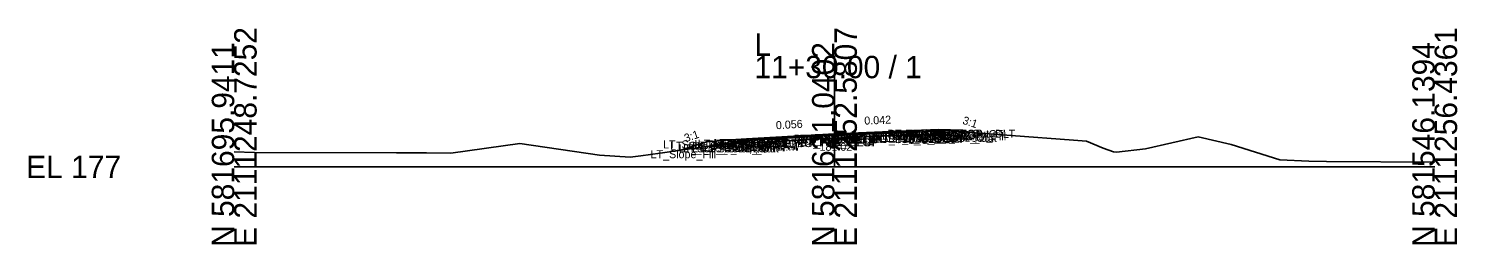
# Model space of a CAD drawing. Extents: x -26 to 3453, y -333 to 9539.
# Drawn here: x -25.7 to 152.8, y 490.3 to 517.3 of the extents above; entities that cross this region are included whole.
import ezdxf

# ---------------------------------------------------------------- set-up
doc = ezdxf.new("R2010")
doc.units = 0
for name, color, linetype in [('Default', 7, 'Continuous'), ('Exist Cross Section Cell', 7, 'Continuous'), ('Exist XS Center Line Elevation Label', 7, 'Continuous'), ('Exist XS Ground Line', 7, 'Continuous'), ('Prop CMT Pvmt Course 1', 7, 'Continuous'), ('Prop CMT Pvmt Course 2', 7, 'Continuous'), ('Prop CMT Pvmt Course 3', 7, 'Continuous'), ('Prop CMT Pvmt Surface', 7, 'Continuous'), ('Prop CMT Pvmt Surface Shoulder', 7, 'Continuous'), ('Prop CMT Pvmt Wedge Surface 1', 7, 'Continuous'), ('Prop CMT Pvmt Wedge Surface 2', 7, 'Continuous'), ('Prop CMT Pvmt Wedge Surface 3', 7, 'Continuous'), ('Prop CMT Shld Paved Course 1', 7, 'Continuous'), ('Prop CMT Shld Paved Course 2', 7, 'Continuous'), ('Prop CMT Shld Paved Course 3', 7, 'Continuous'), ('Prop CMT Slope Grass', 7, 'Continuous'), ('Prop CMT Subgrade Earthwork', 7, 'Continuous'), ('Prop XS SE Text', 7, 'Continuous'), ('Prop XS Side Slope Text', 7, 'Continuous'), ('Scratch_Level_0', 7, 'Continuous')]:
    doc.layers.add(name, color=color, linetype=linetype)

msp = doc.modelspace()

# ---------------------------------------------------------------- linework, layer by layer
at = {"layer": 'Exist Cross Section Cell'}
for p, q in [((75, 500), (75, 513.89)), ((0, 500), (75, 500)), ((75, 500), (150, 500))]:
    msp.add_line(p, q, dxfattribs=at)
at = {"layer": 'Exist XS Ground Line'}
for p, q in [((53.23, 501.72), (65.33, 503.48)), ((65.33, 503.48), (72.05, 503.85)), ((72.05, 503.85), (74.37, 503.99)), ((74.37, 503.99), (75, 504.02)), ((75, 504.02), (76.96, 504.1)), ((76.96, 504.1), (84.62, 504.42)), ((84.62, 504.42), (85.76, 504.54)), ((85.76, 504.54), (86.55, 504.63)), ((86.55, 504.63), (89.28, 504.51)), ((89.28, 504.51), (104.87, 503.34)), ((113.86, 502.27), (120.43, 503.77)), ((120.43, 503.77), (124.56, 502.79)), ((0, 501.87), (2.53, 501.81)), ((2.53, 501.81), (20.26, 501.75)), ((20.26, 501.75), (24.01, 501.78)), ((24.01, 501.78), (27.08, 501.71)), ((27.08, 501.71), (35.69, 502.94)), ((35.69, 502.94), (45.63, 501.49)), ((50.8, 501.39), (53.23, 501.72)), ((104.87, 503.34), (106.51, 503.22)), ((106.51, 503.22), (108.56, 502.33)), ((108.56, 502.33), (109.85, 501.9)), ((109.85, 501.9), (110.23, 501.83)), ((110.23, 501.83), (113.86, 502.27)), ((124.56, 502.79), (130.63, 500.89)), ((45.63, 501.49), (49.49, 501.21)), ((49.49, 501.21), (50.8, 501.39)), ((130.63, 500.89), (134.27, 500.74)), ((134.27, 500.74), (136.5, 500.67)), ((136.5, 500.67), (150, 500.6))]:
    msp.add_line(p, q, dxfattribs=at)
at = {"layer": 'Prop CMT Pvmt Course 1'}
for points in [[(75, 504.12), (64, 503.5)], [(64, 503.5), (64, 503.3)], [(65.39, 503.46), (75, 504)], [(75, 504.12), (86, 504.58)], [(84.67, 504.4), (75, 504)], [(75, 503.91), (75, 504.12)], [(75, 503.91), (75, 504.12)], [(75, 504), (75, 503.91), (75, 503.91)], [(75, 504), (75, 503.91), (75, 503.91)], [(84.67, 504.32), (84.67, 504.4)], [(86, 504.37), (84.67, 504.32)], [(86, 504.58), (86, 504.37)], [(64, 503.3), (65.39, 503.37)], [(65.39, 503.37), (65.39, 503.46)]]:
    msp.add_lwpolyline(points, dxfattribs=at)
at = {"layer": 'Prop CMT Pvmt Course 2'}
for points in [[(84.67, 504.32), (86, 504.37)], [(84.67, 503.98), (84.67, 504.32)], [(86, 504.04), (84.67, 503.98)], [(86, 504.37), (86, 504.04)], [(65.39, 503.37), (64, 503.3)], [(64, 503.3), (64, 502.96)], [(64, 502.96), (65.39, 503.04)], [(65.39, 503.04), (65.39, 503.37)]]:
    msp.add_lwpolyline(points, dxfattribs=at)
at = {"layer": 'Prop CMT Pvmt Course 3'}
for points in [[(84.67, 503.98), (86, 504.04)], [(86, 504.04), (84.67, 503.98)], [(84.67, 503.98), (84.67, 503.98)], [(86, 504.04), (86, 504.04)], [(65.39, 503.04), (64, 502.96)], [(64, 502.96), (65.39, 503.04)], [(64, 502.96), (64, 502.96)], [(65.39, 503.04), (65.39, 503.04)]]:
    msp.add_lwpolyline(points, dxfattribs=at)
at = {"layer": 'Prop CMT Pvmt Surface'}
for points in [[(75, 504.12), (64, 503.5)], [(75, 504.12), (86, 504.58)]]:
    msp.add_lwpolyline(points, dxfattribs=at)
at = {"layer": 'Prop CMT Pvmt Surface Shoulder'}
for points in [[(64, 503.5), (62, 503.39)], [(86, 504.58), (88, 504.66)]]:
    msp.add_lwpolyline(points, dxfattribs=at)
at = {"layer": 'Prop CMT Pvmt Wedge Surface 1'}
for points in [[(64, 503.3), (64, 503.5)], [(75, 504), (65.39, 503.46)], [(75, 504), (84.67, 504.4)], [(84.67, 504.4), (84.67, 504.32)], [(84.67, 504.32), (86, 504.37)], [(86, 504.37), (86, 504.58)], [(65.39, 503.37), (64, 503.3)], [(65.39, 503.46), (65.39, 503.37)]]:
    msp.add_lwpolyline(points, dxfattribs=at)
at = {"layer": 'Prop CMT Pvmt Wedge Surface 2'}
for points in [[(75, 503.91), (64, 503.3)], [(64, 503.3), (64, 503.5)], [(75, 503.91), (86, 504.37)], [(86, 504.37), (86, 504.58)]]:
    msp.add_lwpolyline(points, dxfattribs=at)
at = {"layer": 'Prop CMT Pvmt Wedge Surface 3'}
for points in [[(75, 503.58), (64, 502.96)], [(64, 502.96), (64, 503.5)], [(75, 503.58), (86, 504.04)], [(86, 504.04), (86, 504.58)]]:
    msp.add_lwpolyline(points, dxfattribs=at)
at = {"layer": 'Prop CMT Shld Paved Course 1'}
for points in [[(64, 503.5), (62, 503.39), (61.78, 503.17)], [(64, 503.3), (64, 503.5)], [(86, 504.58), (88, 504.66), (88.2, 504.46)], [(86, 504.37), (86, 504.58)], [(88.2, 504.46), (86, 504.37)], [(61.78, 503.17), (64, 503.3)]]:
    msp.add_lwpolyline(points, dxfattribs=at)
at = {"layer": 'Prop CMT Shld Paved Course 2'}
for points in [[(86, 504.37), (88.2, 504.46), (88.52, 504.14)], [(86, 504.04), (86, 504.37)], [(88.52, 504.14), (86, 504.04)], [(64, 503.3), (61.78, 503.17), (61.43, 502.82)], [(61.43, 502.82), (64, 502.96)], [(64, 502.96), (64, 503.3)]]:
    msp.add_lwpolyline(points, dxfattribs=at)
at = {"layer": 'Prop CMT Shld Paved Course 3'}
for points in [[(86, 504.04), (88.52, 504.14)], [(88.52, 504.14), (86, 504.04)], [(86, 504.04), (86, 504.04)], [(88.52, 504.14), (88.52, 504.14), (88.52, 504.14)], [(64, 502.96), (61.43, 502.82)], [(61.43, 502.82), (64, 502.96)], [(61.43, 502.82), (61.43, 502.82), (61.43, 502.82)], [(64, 502.96), (64, 502.96)]]:
    msp.add_lwpolyline(points, dxfattribs=at)
at = {"layer": 'Prop CMT Slope Grass'}
for points in [[(88, 504.66), (91, 504.61), (91.89, 504.32)], [(62, 503.39), (59, 503.15), (55.79, 502.09)]]:
    msp.add_lwpolyline(points, dxfattribs=at)
at = {"layer": 'Prop CMT Subgrade Earthwork'}
for points in [[(65.39, 503.04), (65.39, 503.48)], [(84.67, 503.98), (84.67, 504.42)], [(84.67, 503.98), (86, 504.04)], [(86, 504.04), (88.52, 504.14)], [(88.52, 504.14), (89.02, 504.65)], [(61.43, 502.82), (60.94, 503.31)], [(64, 502.96), (61.43, 502.82)], [(65.39, 503.04), (64, 502.96)]]:
    msp.add_lwpolyline(points, dxfattribs=at)

# ---------------------------------------------------------------- texts
at = {"layer": 'Default'}
msp.add_text('-', height=0.0001, dxfattribs=at).set_placement((0, 500))
at = {"layer": 'Exist Cross Section Cell'}
for s, p in [('E 2111248.7252', (2.8, 490)), ('E 2111252.5807', (77.8, 490)), ('E 2111256.4361', (152.8, 490)), ('N 581695.9411', (0, 490)), ('N 581621.0402', (75, 490)), ('N 581546.1394', (150, 490))]:
    msp.add_text(s, height=2.8, rotation=90, dxfattribs=at).set_placement(p)
for s, p in [('L', (65, 513.89)), ('11+30.00 / 1', (65, 511.09)), ('EL 177', (-26, 498.6))]:
    msp.add_text(s, height=2.8, dxfattribs=at).set_placement(p)
at = {"layer": 'Exist XS Center Line Elevation Label'}
msp.add_text('181.02', height=1, dxfattribs=at).set_placement((73.13, 502.02))
at = {"layer": 'Prop XS SE Text'}
for s, rotation, p in [('0.056', 3.2052, (67.71, 504.71)), ('0.042', 2.3993, (78.75, 505.28))]:
    msp.add_text(s, height=1, rotation=rotation, dxfattribs=at).set_placement(p)
at = {"layer": 'Prop XS Side Slope Text'}
for rotation, p in [(341.7371, (90.92, 505.42)), (18.2629, (56.41, 503.09))]:
    msp.add_text('3:1', height=1, rotation=rotation, dxfattribs=at).set_placement(p)
at = {"layer": 'Scratch_Level_0'}
for s, p in [('LT_PV1_OEOT', (59.87, 502.5)), ('LT_PV_OEEOP_EG', (59.99, 502.48)), ('LT_Sub Tie Out', (60.55, 502.48)), ('LT_PV1_OEEOP', (60.9, 502.46)), ('RT_PV_IEEOP_EG', (69.92, 503.02)), ('LT_PV_IEEOP_EG', (69.98, 503.02)), ('RT_PV2_IEEOP', (70.71, 502.91)), ('RT_PV3_IEEOP', (70.71, 502.58)), ('LT_PV2_IEEOP', (70.77, 502.91)), ('LT_PV3_IEEOP', (70.77, 502.58)), ('RT_PV1_IEEOP', (70.83, 503)), ('LT_PV1_IEEOP', (70.89, 503)), ('PV2_PGL', (72.35, 502.91)), ('PV1_PGL', (72.47, 503.12)), ('RT_PV_OEEOP_EG', (79.2, 503.42)), ('RT_Sub Tie Out', (79.76, 503.42)), ('RT_PV2_OEEOP', (80, 503.32)), ('RT_PV3_OEEOP', (80, 502.98)), ('RT_Sub_OEEOP', (80.02, 502.98)), ('RT_PV1_OEEOP', (80.12, 503.4)), ('RT_Sub_Trench_Out_DLT', (81.61, 503.65)), ('RT_PV2_OEOT', (81.69, 503.37)), ('RT_PV3_OEOT', (81.69, 503.04)), ('RT_Sub_OEOT', (81.71, 503.04)), ('RT_PV1_OEOT', (81.81, 503.58)), ('RT_Sub_Trench_Out', (82.57, 503.14)), ('RT_PS3_Shelf_Out', (83.12, 503.14)), ('RT_PS1_OEOP', (83.85, 503.66)), ('RT_PS2_OEOP', (83.93, 503.46)), ('RT_PS3_OEOP', (84.25, 503.14)), ('RT_GS_OS_CTL', (86.4, 503.61)), ('RT_Slope_Fill', (88.06, 503.32)), ('LT_Slope_Fill', (52.03, 501.09)), ('LT_Sub_Trench_Out_DLT', (53.59, 502.31)), ('LT_GS_OS_CTL', (54.46, 502.15)), ('LT_Sub_Trench_Out', (55.54, 501.82)), ('LT_PS3_Shelf_Out', (56.08, 501.82)), ('LT_PS3_OEOP', (57.21, 501.82)), ('LT_PS2_OEOP', (57.57, 502.17)), ('LT_PS1_OEOP', (57.91, 502.39)), ('LT_PV2_OEOT', (59.75, 502.3)), ('LT_PV3_OEOT', (59.75, 501.96)), ('LT_Sub_OEOT', (59.77, 501.96)), ('LT_PV2_OEEOP', (60.78, 502.37)), ('LT_PV3_OEEOP', (60.78, 502.04)), ('LT_Sub_OEEOP', (60.8, 502.04))]:
    msp.add_text(s, height=1, dxfattribs=at).set_placement(p)

doc.saveas('drawing.dxf')
